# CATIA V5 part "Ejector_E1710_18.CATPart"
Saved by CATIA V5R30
Part number: Vyhazovac_4x160_5
Nomenclature: E1710/4x160
Description: MEUSBURGER
Property "Material": "1.221"
Publications: "__DrillHole", "Base"
Bounding box of the stored display mesh (mm): x -3.996 to 3.996, y -3.999 to 3.999, z 0 to 152
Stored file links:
  E:\Bakalarka\Model\Forma_v7\Ejector_E1710_18.CATPart
  E:\dev\MoldDesign\intel_a\startup\components\MoldCatalog\Ejector\Meusburger\Ejector_E1710\TableE1710.txt
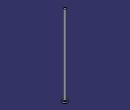
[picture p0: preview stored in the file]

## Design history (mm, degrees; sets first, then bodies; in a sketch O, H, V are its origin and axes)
Parameters
  Ref = "E1710/4x160" {design table}
  D1 = 4 mm {design table}
  D3 = 8 mm {design table}
  L = 160 mm {design table}
  L3 = 3 mm {design table}
  R = 0.3 mm {design table}
  k_d3 = 9 mm {design table}
  k_d1 = 4.2 mm {design table}
  k_F = 0.3 mm {design table}
  kl = 17 mm {design table}
  Mat = "1.221" {design table}
  HeatTreat = "ISO6751" {design table}
  Offset_Parting = 10 mm
  Anti_Rotation = "Normal"
  Anti_Rotation_D = 2.3 mm
  Anti_Rotation_D_Icut = 2.3 mm
  Add_Length_L = 0.8377 mm
  Add_Length_D3 = 0 mm
  SupplierRef = "Meusburger 2017"
  BmpRef = "F_MldEjectorD1"
  DrillHole_Length = 225 mm
  ValidationTest = false
  Anti_Rotation_D_min = 2.3 mm {= OffSet_D1 /2}
  Anti_Rotation_D_max = 3.925 mm {= D3/2-0.075mm}
  Anti_Rotation_D_ref = 2.3 mm {= Anti_Rotation_D}
  Anti_Rotation_D_Icut_ref = 2.3 mm {= Anti_Rotation_D_Icut}
  Anti_Rotation_Ref_Icut = 2.3246 mm
  Offset_L = 20 mm
  D = 4 mm {= D1}
  OffSet_D1 = 4.6 mm {= D1+2*R}
  OffSet_D3 = 9 mm {= D3+1mm}
  XG_Split = 20.5 mm
  YG_Split = 0 mm
  ZG_Split = -198 mm
  DirX_Split = 0 mm
  DirY_Split = 0 mm
  DirZ_Split = 1 mm
Set1 "BaseBody"
  Point1 "Base": (0, 0, 0)
  Plane1: type Offset, RefPlane xy-plane, Offset 225 {= DrillHole_Length}, reversed
  Sketch1 "Sketch.2" on xy-plane, origin (0, 0, 0), H (1, 0, 0), V (0, 1, 0)
    point P1 (-0.46, 1.1623)
    point P2 (0.46, 1.1623)
    construction line L1 (-0.46, 1.1623) -> (0.46, 1.1623)
    point P3 (0.46, -1.1623)
    line L2 (0.46, -1.1623) -> (0.46, 1.1623)
    point P4 (-0.46, -1.1623)
    construction line L3 (0.46, -1.1623) -> (-0.46, -1.1623)
    line L4 (-0.46, 1.1623) -> (-0.46, -1.1623)
    point P5 (-0.21, 1.1623)
    arc A1 centre (-0.21, 1.1623) radius 0.25 from (-0.21, 1.4123) to (-0.46, 1.1623) ccw
    point P7 (0.21, 1.1623)
    point P8 (0.21, 1.4123)
    arc A2 centre (0.21, 1.1623) radius 0.25 from (0.46, 1.1623) to (0.21, 1.4123) ccw
    line L5 (-0.21, 1.4123) -> (0.21, 1.4123)
    point P9 (-0.46, -1.1623)
    arc A3 centre (-0.21, -1.1623) radius 0.25 from (-0.46, -1.1623) to (-0.21, -1.4123) ccw
    point P11 (0.21, -1.4123)
    line L6 (-0.21, -1.4123) -> (0.21, -1.4123)
    point P12 (0.46, -1.1623)
    arc A4 centre (0.21, -1.1623) radius 0.25 from (0.21, -1.4123) to (0.46, -1.1623) ccw
    point P14 (-0.46, 1.1623)
    point P15 (-0.46, -1.1623)
    point P16 (0.46, 1.1623)
    point P17 (0.46, -1.1623)
    reference projected circle E1 centre (0, 0) radius 1.25 from edge [face of Shaft1 from Sketch2.L3 | face of Shaft1 from Sketch2.L4]
    reference projected circle E2 centre (0, 0) radius 1.25 from edge [face of Shaft1 from Sketch2.L3 | face of Shaft1 from Sketch2.L4]
    reference projected circle E3 centre (0, 0) radius 1.25 from edge [face of Shaft1 from Sketch2.L3 | face of Shaft1 from Sketch2.L4]
    reference projected circle E4 centre (0, 0) radius 1.25 from edge [face of Shaft1 from Sketch2.L3 | face of Shaft1 from Sketch2.L4]
    point P18 (-0.46, -1.1623)
    point P19 (-0.21, -1.4123)
    point P20 (0.21, -1.4123)
    point P21 (0.46, -1.1623)
    point P22 (-0.21, -1.4123)
    point P23 (0.21, -1.4123)
    distance P14 P15 = 2.3246 (reference)
    distance P16 P17 = 2.3246 (reference)
    distance L1 P14 = 0 (reference)
    radius A1 = 2
    distance L4 V = 2.31
    distance L2 V = 3.935
    distance L5 L6 = 8
    horizontal: L1 H, L3 H, L5 H
    vertical: L2 V, L4 V
    coincidence: P5 L1, P7 L1, P3 P12, P14 L4, P15 L4, P16 L2, P17 L2, P14 E1, P15 E2, P16 E3, P17 E4, P3 P21, P4 P18, P20 P23, P19 P22
    tangency: A1 L4, A2 L2, A2 L5, A1 L5
    symmetry: P1 P9 H, A1 A3 H, P8 P11 H, L5 L6 H, P2 P12 H, A2 A4 H
  DatumSurface1
Body1 "PartBody" (main body)
  Sketch2 "Sketch.1" on zx-plane, origin (0, 0, 0), H (-1, 0, 0), V (0, 0, 1)
    point P1 (0, 160)
    line L1 (2, 160) -> (0, 160)
    line L2 (2, 3) -> (2, 160)
    line L3 (4, 3) -> (2, 3)
    line L4 (4, 0) -> (4, 3)
    point P5 (0, 0)
    line L5 (0, 0) -> (4, 0)
    point P6 (0, 160)
    axis line L6 (0, 160) -> (0, 0)
    point P7 (0, 0)
    point P8 (2, 3)
    point P9 (2, 3)
    line L7 (0, 160) -> (0, 0)
    distance L5 L3 = 3 {= L3}
    distance L5 L1 = 160 {= L}
    distance L2 L6 = 2 {= D1 /2}
    distance L4 L6 = 4 {= D3 /2}
    coincidence: L6 P5, P1 L6, L5 H, L6 V, P7 O, P6 P1, P8 P9
    vertical: L2 V, L7 V
    horizontal: L1 H
  Shaft1 "Shaft.1": profile Sketch2, axis Sketch2.L6, angle 360
  Pocket1 "Pocket.1": profile Sketch1, direction (0, 0, 1), length 4, outer side, deactivated
  Pocket2 "Pocket.2": profile Sketch1, direction (0, 0, 1), length 4, outer side, deactivated
  Fillet1: radius 0.3 {= R}, on edge [face of Shaft1 from Sketch2.L2 | face of Shaft1 from Sketch2.L3]
  Pocket3: profile face of Shaft1 from Sketch2.L1, direction along face of Shaft1 from Sketch2.L1 reversed, up to face of DatumSurface1
Body2 "__DrillHole"
  Sketch3 "Sketch.3" on face of Shaft1, origin (0, 0, 0), H (1, 0, 0), V (0, -1, 0)
    point P1 (0, 0)
    reference projected point E1 (0, 0) from Point1
    coincidence: E1 P1
  Hole1 "Hole.1": placed by Sketch3, at (0, 0, 0) direction (0, 0, 1), diameter 4.6 {= OffSet_D1}, depth 140 {= L-Offset_L}
  Sketch4 "Sketch.4" on face of Shaft1, origin (0, 0, 0), H (1, 0, 0), V (0, -1, 0)
    point P1 (0, 0)
    reference projected point E1 (0, 0) from Point1
    coincidence: E1 P1
  Hole2 "Hole.2": placed by Sketch4, at (0, 0, 0) direction (0, 0, 1), diameter 4 {= D1}, depth 160 {= L}
  Sketch5 "Sketch.5" on face of Shaft1 from Sketch2.L3, origin (0, 0, 3), H (1, 0, 0), V (0, 1, 0)
    point P1 (0, 0)
    reference projected point E1 (0, 0) from Point1
    coincidence: E1 P1
  Hole3 "Hole.3": placed by Sketch5, at (0, 0, 3) direction (0, 0, -1), diameter 9 {= OffSet_D3}, depth 228 {= L3 +DrillHole_Length}
  Chamfer1: length 0.3 {= k_F}, angle 45, on edge [face of Hole1 | face of Hole3]
  Body3 "__Body.1"
    Pocket4 "Pocket.3": profile Sketch1, direction (0, 0, -1), length 225, opposite side length 3, deactivated
  Assemble1: tool Body3
  Chamfer2: length 0.3 {= k_F}, angle 45, on edge [start face of Pocket4 | face of Hole1], deactivated
  Body4 "__Body.2"
    Pocket5 "Pocket.4": profile Sketch1, direction (0, 0, -1), length 225, opposite side length 3, deactivated
  Assemble2: tool Body4
  Chamfer3: length 0.3 {= k_F}, angle 45, on edge [start face of Pocket5 | face of Hole1], deactivated
Relations
  design table "TableE1710", configuration 187, drives Ref, D1, D3, L, L3, R, k_d3, k_d1, k_F, kl, Mat, HeatTreat
  Offset_L = 20mm (deactivated)
  rule "Cut_Head_rule":
    let sketch_cut (length)
    let PartBody_Pocket_Sketch (Boolean)
    let I_PartBody_Pocket (Boolean)
    let D_PartBody_Pocket (Boolean)
    let N_DrillHole_Hole (Boolean)
    let N_DrillHole_Hole_Sketch (Boolean)
    let I_DrillHole_Pocket (Boolean)
    let D_DrillHole_Pocket (Boolean)
    /* --------------------------------------------------------------------------------------*/
    if Anti_Rotation =="Normal"
    {
    	sketch_cut=Anti_Rotation_D_max
    	PartBody_Pocket_Sketch = false
    	I_PartBody_Pocket = false
    	D_PartBody_Pocket = false
    	N_DrillHole_Hole = true
    	N_DrillHole_Hole_Sketch = true
    	I_DrillHole_Pocket = false
    	D_DrillHole_Pocket = false
    	Chamfer1.Activity= true
    	Chamfer2.Activity= false
    	Chamfer3.Activity= false
    }
    if Anti_Rotation == "I_Cut"
    {
    	sketch_cut=Anti_Rotation_D_Icut_ref
    	PartBody_Pocket_Sketch = true
    	I_PartBody_Pocket = true
    	D_PartBody_Pocket = false
    	N_DrillHole_Hole = false
    	N_DrillHole_Hole_Sketch = false
    	I_DrillHole_Pocket = true
    	D_DrillHole_Pocket = false
    	Chamfer1.Activity= false
    	Chamfer2.Activity= true
    	Chamfer3.Activity= false
    }
    if Anti_Rotation =="D_Cut"
    {
    	sketch_cut=Anti_Rotation_D_max
    	PartBody_Pocket_Sketch = true
    	I_PartBody_Pocket = false
    	D_PartBody_Pocket = true
    	N_DrillHole_Hole = false
    	N_DrillHole_Hole_Sketch = false
    	I_DrillHole_Pocket = false
    	D_DrillHole_Pocket = true
    	Chamfer1.Activity= false
    	Chamfer2.Activity= false
    	Chamfer3.Activity= true
    }
    /* --------------------------------------------------------------------------------------*/
    Sketch1.distance(L2 V) = sketch_cut+0.01mm
    Sketch1.distance(L4 V) =Anti_Rotation_D_ref+0.01mm
    Sketch1.radius(A1) =D/2
    Pocket4.FirstLimit.Depth = DrillHole_Length
    Pocket5.FirstLimit.Depth = DrillHole_Length
    Pocket1.FirstLimit.Depth = L3+1mm
    Pocket2.FirstLimit.Depth = L3+1mm
    Pocket4.SecondLimit.Depth = L3
    Pocket5.SecondLimit.Depth =L3
    Pocket1.Activity = I_PartBody_Pocket
    Pocket2.Activity = D_PartBody_Pocket
    Sketch1.Activity =PartBody_Pocket_Sketch
    Hole3.Activity= N_DrillHole_Hole
    Sketch5.Activity = N_DrillHole_Hole_Sketch
    Pocket4.Activity = I_DrillHole_Pocket
    Pocket5.Activity  = D_DrillHole_Pocket
  rule "Anti_Rotation_Icut_constrain":
    let Ref1(length)
    let Ref2(length)
    let Ref3(length)
    let Diam1(length)
    let Diam2(length)
    let Add_Length_Lmin (length)
    Ref1=Sketch1.distance(P14 P15)
    Ref2=Sketch1.distance(P16 P17)
    Diam1=D
    Diam2=D3
    /* --------------------------------------------------------------------*/
    if Ref1 >Ref2
    	Anti_Rotation_Ref_Icut = Ref1
    else
    	Anti_Rotation_Ref_Icut  =Ref2
    Add_Length_D3 .InferiorRange=Anti_Rotation_Ref_Icut /2+Diam1/2 -Diam2/2
    if Add_Length_D3 .InferiorRange<0mm
    	Add_Length_D3 .InferiorRange=0mm
    if ValidationTest == "true"
    	Ref3   = 2*Add_Length_L +Anti_Rotation_Ref_Icut  +2*Diam1/2
    else
    	Ref3  =Diam2+2*Add_Length_D3
    if Ref3 <Diam2
    {
    	Ref3 =Diam2
    }
    /* --------------------------------------------------------------------*/
    Sketch1.distance(L5 L6) = Ref3
    Add_Length_L .InferiorRange=Diam2/2-Anti_Rotation_Ref_Icut/2-Diam1/2
    Add_Length_Lmin=Diam2/2-Anti_Rotation_Ref_Icut/2-Diam1/2
    if Add_Length_Lmin<0mm
    	Add_Length_L .InferiorRange=0mm
    else
    	Add_Length_L .InferiorRange=Add_Length_Lmin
